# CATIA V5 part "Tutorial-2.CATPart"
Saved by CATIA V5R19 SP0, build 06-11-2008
Part number: tut2
Bounding box of the stored display mesh (mm): x -104.999 to 104.999, y -155 to 550, z -22.499 to 22.486
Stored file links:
  D:\Shriniwas\v5_r19\Part files\c10\c10tut2.CATPart
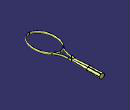
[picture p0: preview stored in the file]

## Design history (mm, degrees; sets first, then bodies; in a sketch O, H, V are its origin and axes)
Body1 (main body)
  Sketch1 on xy-plane, origin (0, 0, 0), H (1, 0, 0), V (0, 1, 0)
    ellipse A1 centre (0, 0) semi-axes 150, 100 rotation 90
    point P1 (100, 0)
    "Radius" A1 = 150
    "Radius" A1 = 100
    coincidence: P1 H, A1 P1
    vertical: A1 V
  Sketch2 on zx-plane, origin (0, 0, 0), H (-1, 0, 0), V (0, 0, 1)
    point P1 (100, 0)
    ellipse A1 centre (100, 0) semi-axes 10, 5 rotation 90
    point P2 (105, 0)
    reference projected line E1 (-100, 0) -> (100, 0) from Sketch1.A1
    "Radius" A1 = 10
    "Radius" A1 = 5
    distance V P1 = 100
    coincidence: P2 H, A1 P2, P1 E1
    vertical: A1 V
  Sweep1: type Unspec, Guide Sketch1, Profile Sketch2
  Sketch3 on xy-plane, origin (0, 0, 0), H (1, 0, 0), V (0, 1, 0)
    line L1 (15, 275) -> (15, 245)
    point P1 (15, 275)
    arc A1 centre (215, 245) radius 200 from (15, 245) to (55, 125) ccw
    point P4 (55, 125)
    radius A1 = 200
    distance L1 V = 15
    distance H P1 = 275
    distance H P4 = 125
    distance P4 V = 55
    vertical: L1 V
    tangency: A1 L1
  Plane1: type Normal, Curve Sketch3, RefPoint Sketch3.P1
  Sketch4 on Plane1, origin (0, 275, 0), H (1, 0, 0), V (0, 0, 1)
    point P1 (15, 0)
    ellipse A1 centre (15, 0) semi-axes 8.75, 4.5 rotation 90
    reference projected point E1 (15, 0) from Sketch3.P1
    "Radius" A1 = 8.75
    "Radius" A1 = 4.5
    vertical: A1 V
    coincidence: P1 E1
  Sweep2: type Unspec, Guide Sketch3, Profile Sketch4
  Symmetry1: Reference yz-plane, ToTransfor Sweep2
  Sketch5 on Plane1, origin (0, 275, 0), H (1, 0, 0), V (0, 0, 1)
    projected curve E1 from Sketch4.A1
    projected curve E2 from Sketch4.A1
    projected curve E3 from edge of Symmetry1
    projected curve E4 from edge of Symmetry1
    line L1 (11.75, 6.052) -> (-11.75, 6.052)
    point P1 (11.75, 6.052)
    point P2 (-11.75, 6.052)
    point P3 (-11.75, -6.052)
    point P4 (11.75, -6.052)
    line L2 (11.75, -6.052) -> (-11.75, -6.052)
    point P5 (-11.75, -6.052)
    length L1 = 23.5
    horizontal: L1 H
    coincidence: P1 E1, P2 E3, L2 P5
    symmetry: P2 P3 H, P1 P4 H, L1 L2 H
  Plane2: type Offset, Offset 425, RefPlane zx-plane
  Sketch6 on Plane2, origin (0, 425, 0), H (-1, 0, 0), V (0, 0, 1)
    ellipse A1 centre (0, 0) semi-axes 22.5, 20 rotation 0
    point P1 (22.5, 0)
    point P2 (0, 20)
    point P3 (-11.75, 17.0562)
    point P4 (11.75, 17.0562)
    point P5 (11.75, -17.0562)
    point P6 (-11.75, -17.0562)
    "Radius" A1 = 22.5
    "Radius" A1 = 20
    distance V P3 = 11.75
    distance P3 P4 = 23.5
    distance P6 P5 H = 23.5
    distance P6 V = 11.75
    coincidence: P1 H, P2 V, A1 P1, A1 P2, P3 A1, P4 A1, P6 A1, A1 P5
    horizontal: A1 H
  Loft1: Sections (Sketch5; Sketch6.A1), SectionCouplingPoints ({coupling CouplingPoints (vertex [element of Sketch5 | element of Sketch5]; Sketch6.P4)}; {coupling CouplingPoints (vertex [element of Sketch5 | element of Sketch5]; Sketch6.P5)}; {coupling CouplingPoints (vertex [element of Sketch5 | element of Sketch5]; Sketch6.P6)}; {coupling CouplingPoints (vertex [element of Sketch5 | element of Sketch5]; Sketch6.P3)})
  Plane3: type Offset, Offset 550, RefPlane zx-plane
  Sketch7 on Plane3, origin (0, 550, 0), H (-1, 0, 0), V (0, 0, 1)
    circle A1 centre (0, 0) radius 22.5
    radius A1 = 22.5
  Blend1: StartLimit {blendlimit Curve edge of Loft1, Point {extremum Reference edge of Loft1, Direction (1, 2, 3)}}, EndLimit {blendlimit Curve Sketch7, Point {extremum Reference Sketch7, Direction (1, 2, 3)}}
  Fill1: Boundary edge of Blend1
  Fill2: Boundary Sketch5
